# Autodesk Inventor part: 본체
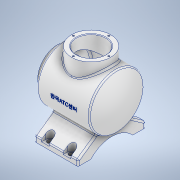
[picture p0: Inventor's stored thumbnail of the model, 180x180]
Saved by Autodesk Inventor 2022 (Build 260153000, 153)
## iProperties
Created: 2023-04
Part Number: 본체
Material: 알루미늄 6061
Document SubType Name: Modeling
Designer: ADMIN_PC
Density: 2.7 g/cm^3
Appearance: 알루미늄 - 평지
Author: ADMIN_PC
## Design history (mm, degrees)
sketch "스케치1"
  geometry: L1 (-85.64, 0)-(92.662, 0) reference; L2 (0, -20.644)-(0, 92.638) reference; L3 (-48.168, 50)-(48.168, 50); L4 (48.168, 50)-(48.168, 0); L5 (48.168, 0)-(-48.168, 0); L6 (-48.168, 0)-(-48.168, 50); L7 (-48.168, 0)-(-60.168, 0); L8 (-60.168, 0)-(-60.168, 36); L9 (-60.168, 36)-(-48.168, 36); L10 (-48.168, 36)-(-48.168, 0); L11 (48.168, 0)-(59.832, 0); A1 r 113 centre (-53.168, 0) between (59.744, -4.46) and (32.36, 73.851); 3 further points
  constraints: 18 end point, 4 parallel, 4 point on circle, 3 point on line, 2 horizontal, 2 perpendicular, 1 centre point, 1 other
  dimensions: "d1" = 113 radius of A1; "d2" = 108 distance from line of L11.end L6; "d3" = 100 diameter of L3 L5; "d4" = 72 diameter of L9 L5; "d5" = 120 distance from line of L11.end L8
revolve "회전1" sketch "스케치1" stored, may be unused: angle "d6" = 90 deg
sketch "스케치2"
  geometry: L1 (60.168, 36)-(60.168, -36) reference; L2 (82.8, 0)-(-54.4, 0) reference; C1 r 36 at (-1.832, 0); 1 further point
  constraints: 1 centre point, 1 point on line
  dimensions: "d7" = 62 distance from line of L1 C1.centre; "d8" = 72 diameter of C1
extrude "돌출1" join sketch "스케치2" distance "d9" = 65; taper "d10" = 0 deg
node "작업 평면1"
sketch "스케치3"
  geometry: L1 (40.168, 62)-(-39.832, 62); L2 (-39.832, 62)-(-39.832, -62); L3 (-39.832, -62)-(40.168, -62); L4 (40.168, -62)-(40.168, 62); L5 (60.168, 36)-(60.168, -36) reference; L6 (84.168, 0)-(-83.832, 0) reference; 1 further point
  constraints: 8 end point, 2 parallel, 1 horizontal, 1 perpendicular, 1 other
  dimensions: "d12" = 20 distance between parallel lines of L5 L4; "d13" = 124 distance of L3.end L1.start; "d14" = 80 distance between parallel lines of L2 L4
extrude "돌출2" join sketch "스케치3" distance "d15" = 10; taper "d16" = 0 deg
sketch "스케치4"
  geometry: L1 (124, 10)-(0, 10) reference; L2 (0, 10)-(49.774, 44.852); L3 (49.774, 44.852)-(74.226, 44.852); L4 (124, 0)-(124, 10) reference; L5 (74.226, 44.852)-(124, 10); L6 (0, 0)-(0, 10) reference; 1 further point
  constraints: 6 end point, 1 horizontal
  dimensions: "d17" = 55 deg angle of L5 L4; "d18" = 55 deg angle of L2 L6; "d19" = 34.85185 distance between parallel lines of L1 L3
extrude "돌출3" join sketch "스케치4" distance "d20" = 80; taper "d21" = 0 deg
sketch "스케치5"
  geometry: L1 (62, 153.549)-(62, -9.987); L2 (23.5, 0)-(100.5, 0); L3 (100.5, 0)-(100.5, 17); L4 (100.5, 17)-(23.5, 17); L5 (23.5, 17)-(23.5, 0); L6 (124, 0)-(0, 0) reference; A1 r 52.096 centre (62, -35.096) between (100.5, 0) and (23.5, 0); 3 further points
  constraints: 10 end point, 2 parallel, 2 point on circle, 1 centre point, 1 collinear, 1 horizontal, 1 perpendicular, 1 point on line, 1 vertical, 1 other
  dimensions: "d22" = 77 distance between parallel lines of L3 L5; "d23" = 17 distance between parallel lines of L2 L4; "d24" = 52.09559 radius of A1
extrude "돌출4" cut sketch "스케치5" extent not by distance; stored distance "d25" = 0; taper "d26" = 0 deg
node "작업 평면3"
sketch "스케치6"
  geometry: L1 (-19.832, -54)-(-19.832, -74.505); L2 (-12.832, -54)-(-12.832, -74.505); L3 (-26.832, -74.505)-(-26.832, -54); L4 (-39.832, -62)-(40.168, -62) reference; L5 (-39.832, -38.5)-(-39.832, -62) reference; L6 (84.168, 0)-(-83.832, 0) reference; L7 (0, -111.2)-(0, 90.867) reference; L8 (20.168, -54)-(20.168, -74.505); L9 (13.168, -54)-(13.168, -74.505); L10 (27.168, -74.505)-(27.168, -54); L11 (20.168, 54)-(20.168, 74.505); L12 (27.168, 74.505)-(27.168, 54); L13 (-19.832, 54)-(-19.832, 74.505); L14 (-26.832, 74.505)-(-26.832, 54); L15 (13.168, 54)-(13.168, 74.505); L16 (-12.832, 54)-(-12.832, 74.505); A1 r 7 centre (-19.832, -54) between (-12.832, -54) and (-26.832, -54); A2 r 7 centre (-19.832, -74.505) between (-26.832, -74.505) and (-12.832, -74.505); A3 r 7 centre (20.168, -54) between (27.168, -54) and (13.168, -54); A4 r 7 centre (20.168, -74.505) between (13.168, -74.505) and (27.168, -74.505); A5 r 7 centre (20.168, 54) between (13.168, 54) and (27.168, 54); A6 r 7 centre (-19.832, 54) between (-26.832, 54) and (-12.832, 54); A7 r 7 centre (20.168, 74.505) between (27.168, 74.505) and (13.168, 74.505); A8 r 7 centre (-19.832, 74.505) between (-12.832, 74.505) and (-26.832, 74.505); 5 further points
  constraints: 32 end point, 16 point on circle, 14 symmetric about line, 8 centre point, 8 tangent, 2 midpoint, 2 parallel, 2 vertical, 4 other
  dimensions: "d28" = 14 distance between parallel lines of L2 L3; "d29" = 8 distance from line of L4 L1.start; "d30" = 20 distance between parallel lines of L5 L1; "d31" = 20.50493 distance of L3.start L3.end; "d32" = 8 distance from line of L4 L8.start; "d33" = 14 distance between parallel lines of L9 L10; "d34" = 40 distance between parallel lines of L8 L1; "d35" = 20.50493 distance of L10.start L10.end
extrude "돌출5" cut sketch "스케치6" distance "d36" = 20.50493 (= d35); taper "d37" = 0 deg
sketch "스케치7"
  geometry: L1 (-84.168, 0)-(83.832, 0) reference; L2 (0, -105.4)-(0, 93.4) reference; L3 (-60.168, -36)-(-60.168, 36) reference; L4 (-60.168, 0)-(-41.168, 0); L5 (-41.168, 0)-(-41.168, 27); L6 (-41.168, 27)-(-60.168, 27); L7 (-60.168, 27)-(-60.168, 0); L8 (-41.168, 0)-(43.718, 0); L9 (43.718, 0)-(43.718, 43); L10 (43.718, 43)-(-41.168, 43); L11 (-41.168, 43)-(-41.168, 0); L12 (43.718, 0)-(52.832, 0); A1 r 113 centre (-53.168, 0) between (48.168, -50) and (48.168, 50) reference; A2 r 106 centre (-53.168, 0) between (41.891, -46.903) and (41.891, 46.903); 5 further points
  constraints: 18 end point, 4 parallel, 4 point on circle, 2 horizontal, 2 perpendicular, 1 centre point, 1 collinear, 1 midpoint
  dimensions: "d38" = 7 radial gap between concentric circles of A1 A2; "d39" = 19 distance between parallel lines of L11 L3; "d40" = 54 diameter of L6 L1; "d41" = 86 diameter of L10 L1
revolve "회전2" sketch "스케치7" stored, may be unused: angle "d42" = 90 deg
sketch "스케치8"
  geometry: C1 r 36 at (0, 0) reference; C2 r 27 at (0, 0); 1 further point
  constraints: 1 centre point
  dimensions: "d43" = 54 diameter of C2
extrude "돌출6" cut sketch "스케치8" distance "d44" = 65; taper "d45" = 0 deg
sketch "스케치9" dims "d46" = 65
  geometry: L1 (0, -105.4)-(0, 93.4) reference; 3 further points
  constraints: 1 coincident, 1 point on line, 1 vertical alignment, 2 other
hole "구멍1" sketch "스케치9" at (0, 32.5) diameter "d47" = 3.242; stored, may be unused: countersink angle "d51" = 90 deg, drill point angle "d53" = 118 deg; dims "d48" = 8, "d49" = 4, "d50" = 2, "d52" = 10
sketch "스케치10" dims "d57" = 65
  geometry: L1 (0, 0)-(0, 34.763); C1 r 27 at (0, 0) reference; 2 further points
  constraints: 2 end point, 1 point on line, 1 vertical, 1 vertical alignment, 2 other
hole "구멍2" sketch "스케치10" at (0, 32.5) diameter "d58" = 3.242; stored, may be unused: countersink angle "d62" = 90 deg, drill point angle "d64" = 118 deg; dims "d59" = 8, "d60" = 4, "d61" = 2, "d63" = 10
fillet "모깎기1" dims "d68" = 3
chamfer "모따기1" distance "d69" = 1; stored, may be unused: second distance "d70" = 2, angle "d71" = 45 deg
sketch "스케치11"
  geometry: A1 r 7 centre (-20.168, -54) between (-13.168, -54) and (-27.168, -54) reference; A2 r 7 centre (19.832, -54) between (26.832, -54) and (12.832, -54) reference; A3 r 7 centre (19.832, 54) between (12.832, 54) and (26.832, 54) reference; A4 r 7 centre (-20.168, 54) between (-27.168, 54) and (-13.168, 54) reference; 5 further points
  constraints: 4 coincident
hole "구멍3" sketch "스케치11" at (19.832, 54), (-20.168, 54), (-20.168, -54), (19.832, -54) diameter "d72" = 9; stored, may be unused: countersink angle "d76" = 90 deg, drill point angle "d78" = 118 deg; dims "d73" = 8, "d74" = 4, "d75" = 2, "d77" = 10
node "작업 평면4"
sketch "스케치12"
  geometry: L1 (-60.168, -36)-(-60.168, 36) reference; L2 (-84.168, 0)-(83.832, 0) reference; 2 further points
  constraints: 1 point on line, 1 other
  dimensions: "d79" = 62 distance from line of L1 point (1.832, 0)
feature "엠보싱1" sketch "스케치12" dims "d1" = 113, "d2" = 108, "d3" = 100, "d4" = 72, "d5" = 120, "d80" = 0.5, "d81" = 0
node "솔리드1"
pattern_circular "원형 패턴1" dims angle "d55" = 360 deg
pattern_circular "원형 패턴2" dims angle "d66" = 360 deg
feature "A9D066F2-1C7D-4E18-AEED-F7BC21143FA4" dims "d72" = 9, "d73" = 8, "d74" = 4, "d75" = 2, "d76" = 90 deg, "d77" = 10, "d78" = 118 deg
other parameters: "d11" = -77, "d27" = -71
